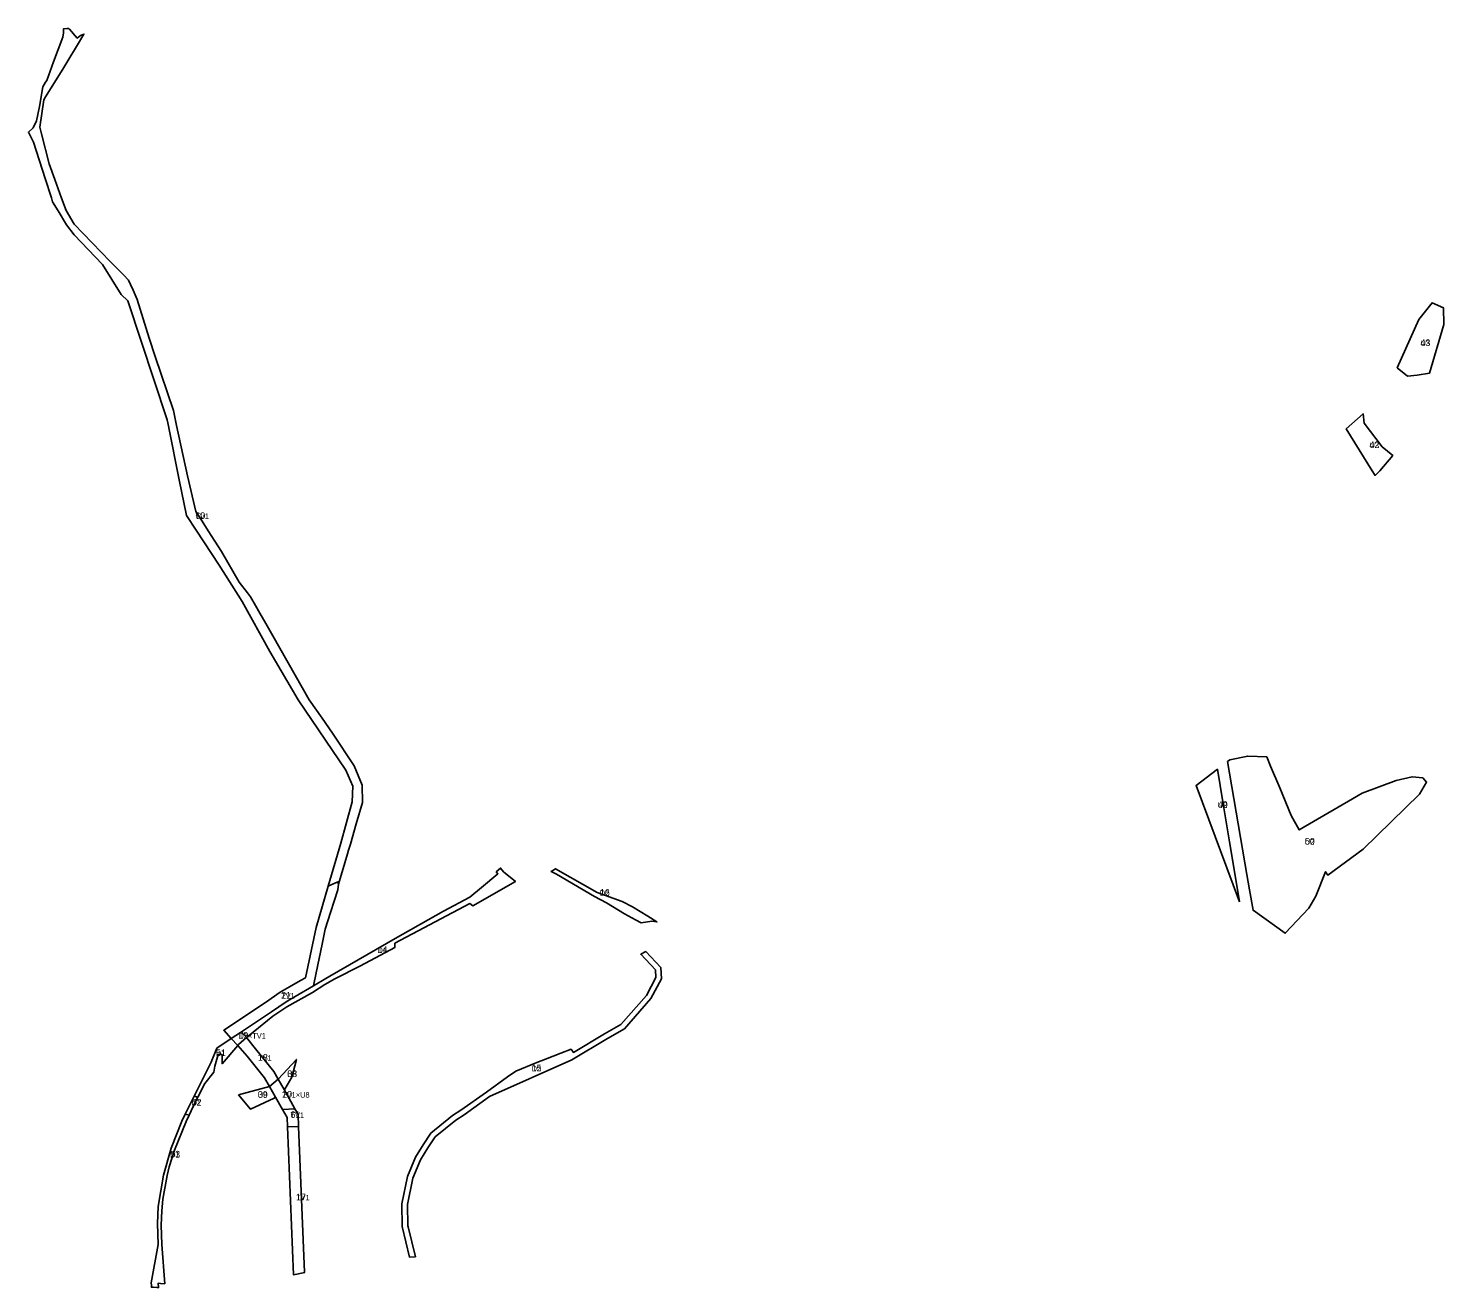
# Model space of a CAD drawing. Extents: x -521229 to -518220, y -1182332 to -1179899.
# Drawn here: x -519495 to -518220, y -1182332 to -1181197 of the extents above; entities that cross this region are included whole.
import ezdxf

# ---------------------------------------------------------------- set-up
doc = ezdxf.new("R2010")
doc.units = 0
for name, color, linetype in [('96120023', 7, 'Continuous'), ('96140023', 7, 'Continuous'), ('ID_VPO', 7, 'Continuous'), ('ID_VPS', 7, 'Continuous')]:
    doc.layers.add(name, color=color, linetype=linetype)

msp = doc.modelspace()

# ---------------------------------------------------------------- linework, layer by layer
at = {"layer": '96120023'}
for points in [[(-519215.9, -1181968.5), (-519216.5, -1181966.3), (-519225.2, -1181970.1), (-519213.9, -1181931.5), (-519203.5, -1181894.2), (-519203.1, -1181880), (-519209.3, -1181865.7), (-519252.2, -1181802.5), (-519277.7, -1181758.8), (-519302.6, -1181713.9), (-519323.6, -1181681.2), (-519344.2, -1181649.6), (-519352.9, -1181636.3), (-519359.6, -1181604.3), (-519368.7, -1181557.5), (-519368.7, -1181557.2), (-519370.4, -1181550.3), (-519405.7, -1181443.1), (-519411.7, -1181437.2), (-519428.5, -1181410.3), (-519454, -1181383.6), (-519461, -1181374.5), (-519468.4, -1181361.8), (-519473.5, -1181353.7), (-519474.6, -1181350.3), (-519480.4, -1181332.8), (-519490.9, -1181300.1), (-519495.4, -1181291), (-519491.1, -1181287.2), (-519488, -1181280.9), (-519485.4, -1181267.9), (-519482.4, -1181250.1), (-519479.9, -1181246), (-519478.9, -1181244.5), (-519472.7, -1181227.6), (-519464.3, -1181205.3), (-519463.8, -1181201.4), (-519463.7, -1181198.7), (-519463.8, -1181198), (-519460.8, -1181197.6), (-519459, -1181197.5), (-519458.4, -1181198.2), (-519451.4, -1181206.3), (-519448.5, -1181203.9), (-519445.4, -1181202.7), (-519450.3, -1181210.8), (-519460.7, -1181228.4), (-519464.3, -1181234.2), (-519480, -1181259.1), (-519481.6, -1181261.8), (-519485, -1181286.5), (-519483.7, -1181292.5), (-519476.7, -1181319.5), (-519471.5, -1181333.7), (-519465.4, -1181350.4), (-519461.3, -1181361.7), (-519454.1, -1181373.8), (-519421.6, -1181407.6), (-519412.6, -1181416.6), (-519409.4, -1181419.9), (-519405.1, -1181424.3), (-519403.4, -1181428.1), (-519401.1, -1181433.2), (-519397.5, -1181441.8), (-519386.5, -1181476.6), (-519381, -1181493), (-519364.6, -1181541.6), (-519362, -1181555.4), (-519351.9, -1181600.5), (-519344.5, -1181632.7), (-519338.9, -1181641.3), (-519333.4, -1181650.1), (-519321.4, -1181668.9), (-519305.3, -1181696.4), (-519298, -1181706), (-519296.2, -1181708.4), (-519295.1, -1181709.7), (-519290.8, -1181717.3), (-519286.8, -1181724.3), (-519281.3, -1181733.6), (-519242.4, -1181802.3), (-519230.7, -1181819), (-519221.3, -1181832.4), (-519201.8, -1181861.7), (-519194.5, -1181879.2), (-519194.4, -1181895), (-519199.9, -1181914), (-519205.1, -1181932.4), (-519206.8, -1181937.9), (-519207.7, -1181941.2)], [(-519263, -1182074.3), (-519254.9, -1182069.6), (-519238.3, -1182059.9), (-519227.2, -1182053.5), (-519223.6, -1182051.4), (-519165, -1182017.4), (-519121.4, -1181992.9), (-519097.7, -1181980.1), (-519087, -1181971.3), (-519072.3, -1181959), (-519073.7, -1181957.4), (-519069.8, -1181954), (-519067.1, -1181957.2), (-519056.5, -1181966.1), (-519094.9, -1181987.8), (-519097.7, -1181985.9), (-519165.3, -1182021.7), (-519165.2, -1182025.6), (-519196.2, -1182041.9), (-519219.1, -1182053.7), (-519228.3, -1182058.9), (-519239.4, -1182065.9), (-519262.5, -1182078.9), (-519275.1, -1182087.4), (-519292.8, -1182101.6), (-519298.8, -1182106.7), (-519303.2, -1182101.3), (-519276.2, -1182083.4)], [(-518937.3, -1181997.3), (-518929, -1182002.4), (-518933.6, -1182001.9), (-518943.3, -1182003.3), (-518948.4, -1182000.5), (-518958.2, -1181995.2), (-518974.5, -1181985.3), (-518985.3, -1181979.5), (-519019.5, -1181959.3), (-519024.4, -1181957.1), (-519020.5, -1181954.6), (-518982.7, -1181976), (-518960.3, -1181984.1), (-518951, -1181988.9)], [(-519216.5, -1181966.3), (-519215.9, -1181968.5), (-519216.6, -1181973.6), (-519223.2, -1181994.1), (-519227.9, -1182009), (-519230.7, -1182022.6), (-519235.9, -1182048.3), (-519238.3, -1182059.9), (-519254.9, -1182069.6), (-519263, -1182074.3), (-519276.2, -1182083.4), (-519303.2, -1182101.3), (-519304.1, -1182101.9), (-519312.5, -1182107.5), (-519319.3, -1182100), (-519281.8, -1182075.1), (-519268.4, -1182065.8), (-519260, -1182061), (-519250.1, -1182055.2), (-519245.6, -1182052.7), (-519236.1, -1182007.6), (-519225.2, -1181970.1)], [(-519153.4, -1182276.3), (-519153.2, -1182277.2), (-519146.6, -1182304.1), (-519152, -1182304.4), (-519158.4, -1182276.9), (-519158.7, -1182256.5), (-519153.6, -1182231.9), (-519146.4, -1182214.4), (-519139.6, -1182203.3), (-519132.6, -1182192.7), (-519113.1, -1182176.9), (-519105.6, -1182172), (-519082.7, -1182155.7), (-519063.6, -1182141.9), (-519056.2, -1182136.9), (-519037.1, -1182129.2), (-519029.5, -1182126.1), (-519015.7, -1182120.8), (-519006.3, -1182117.1), (-519004.2, -1182120), (-518976.2, -1182103.2), (-518961.4, -1182094.7), (-518938.5, -1182068.6), (-518930.1, -1182052.6), (-518930.3, -1182045.5), (-518943.5, -1182031.6), (-518939, -1182029.1), (-518925.4, -1182043.5), (-518925, -1182053.8), (-518934.4, -1182071.5), (-518958.2, -1182098.6), (-518973.6, -1182107.5), (-519005.6, -1182126.6), (-519079.8, -1182159.8), (-519102.8, -1182176.1), (-519110.2, -1182181), (-519128.9, -1182196.1), (-519135.4, -1182206), (-519141.9, -1182216.7), (-519148.8, -1182233.3), (-519153.7, -1182257)], [(-519304.1, -1182101.9), (-519303.2, -1182101.3), (-519298.8, -1182106.7), (-519306, -1182112.9), (-519306.7, -1182113.8), (-519312.5, -1182107.5)], [(-519325.6, -1182116.1), (-519312.5, -1182107.5), (-519306.7, -1182113.8), (-519320.9, -1182130.2), (-519320.8, -1182121.9), (-519324.4, -1182121.8), (-519327.5, -1182132.3), (-519328.2, -1182137.9), (-519336.5, -1182148), (-519342.7, -1182160.2), (-519346.1, -1182159.4), (-519330.8, -1182128.7)], [(-519274.2, -1182137.3), (-519270.3, -1182144.2), (-519278.2, -1182150.6), (-519282.5, -1182142.9), (-519298.1, -1182123.5), (-519306.7, -1182113.8), (-519306, -1182112.9), (-519298.8, -1182106.7), (-519290.8, -1182116.7)], [(-519265, -1182153.5), (-519259, -1182164.2), (-519255.3, -1182170.8), (-519266.4, -1182171.5), (-519272.8, -1182160.2), (-519278.2, -1182150.6), (-519270.3, -1182144.2)], [(-519346.1, -1182159.4), (-519342.7, -1182160.2), (-519344.7, -1182164.2), (-519350.4, -1182176.4), (-519354, -1182175.6), (-519347.5, -1182162.4)], [(-519357, -1182181.9), (-519354, -1182175.6), (-519350.4, -1182176.4), (-519353.1, -1182182.1), (-519363.6, -1182208.1), (-519368.5, -1182223), (-519370.4, -1182230.8), (-519374.2, -1182252.1), (-519375.2, -1182262.6), (-519375.7, -1182275.6), (-519375, -1182293.1), (-519372.5, -1182328.4), (-519376.2, -1182328.1), (-519378.5, -1182328), (-519378.1, -1182331.9), (-519379.7, -1182331.8), (-519382.8, -1182331.6), (-519384.5, -1182331.5), (-519384.3, -1182329.7), (-519384.8, -1182327.5), (-519378.5, -1182293.1), (-519378.9, -1182274.2), (-519378.3, -1182258.9), (-519373.6, -1182230.6), (-519366.8, -1182206.1)], [(-519255.3, -1182170.8), (-519252.4, -1182175.8), (-519252, -1182186.8), (-519262, -1182187.1), (-519262.3, -1182178.6), (-519266.4, -1182171.5)], [(-519252, -1182186.8), (-519246.6, -1182317.8), (-519246.4, -1182318.2), (-519256.5, -1182320.2), (-519262, -1182187.1)]]:
    msp.add_lwpolyline(points, close=True, dxfattribs=at)
at = {"layer": '96140023'}
for points in [[(-518252.5, -1181510.9), (-518261.8, -1181503.3), (-518242.4, -1181459.7), (-518230.4, -1181444.7), (-518220.1, -1181449.3), (-518220, -1181464.4), (-518232.9, -1181508.2), (-518243.8, -1181510)], [(-518284.3, -1181596.1), (-518307.8, -1181558.4), (-518292.6, -1181544.7), (-518291.5, -1181553.1), (-518275.5, -1181574.4), (-518265.9, -1181582.4), (-518277.6, -1181596.1), (-518281.8, -1181600.2)], [(-518412.8, -1181856.5), (-518396.5, -1181853), (-518379.5, -1181853.8), (-518376.1, -1181862.1), (-518367.7, -1181881.6), (-518357.5, -1181906.6), (-518350.2, -1181919.6), (-518302.1, -1181891.7), (-518293.4, -1181886.5), (-518262.9, -1181874.9), (-518248.5, -1181871.6), (-518238.8, -1181872.7), (-518235.4, -1181876.6), (-518241.7, -1181887.3), (-518292.4, -1181936.8), (-518324.5, -1181960.2), (-518326.4, -1181957.3), (-518335.1, -1181979.1), (-518341.4, -1181989.9), (-518362.7, -1182012.6), (-518391.7, -1181991.9), (-518394.9, -1181973.6), (-518397.3, -1181959.6), (-518414.9, -1181858)], [(-518403.9, -1181984.2), (-518443.1, -1181879.4), (-518423.9, -1181864.9), (-518418.9, -1181894.4), (-518412.9, -1181930.3), (-518408.7, -1181955.2)], [(-519265, -1182153.5), (-519270.3, -1182144.2), (-519253.9, -1182126.3), (-519257.9, -1182142.4), (-519264.4, -1182153)], [(-519305.9, -1182158.1), (-519278.2, -1182150.6), (-519272.8, -1182160.2), (-519272.8, -1182160.2), (-519273.8, -1182161.1), (-519295.3, -1182171.1)], [(-519265, -1182153.5), (-519259, -1182164.2), (-519255.3, -1182170.8), (-519266.4, -1182171.5), (-519272.8, -1182160.2), (-519278.2, -1182150.6), (-519270.3, -1182144.2)]]:
    msp.add_lwpolyline(points, close=True, dxfattribs=at)

# ---------------------------------------------------------------- texts
at = {"layer": '96120023'}
for s, rotation, p in [('TV1', 360, (-519344.9, -1181639.5)), ('D2', 0, (-518980.4, -1181978.9)), ('D1', 0, (-519180.8, -1182030.4)), ('TV1', 0, (-519267.6, -1182071.5)), ('D1×TV1', 360, (-519306.1, -1182107.6)), ('D1', 360, (-519326.4, -1182123.3)), ('TV1', 0, (-519288.5, -1182127.5)), ('D2', 360, (-519041.9, -1182137)), ('TV1×U8', 360, (-519266.7, -1182160.7)), ('D1', 360, (-519348.3, -1182167.9)), ('TV1', 0, (-519259.2, -1182179)), ('D1', 360, (-519367.6, -1182214.7)), ('TV1', 360, (-519254.2, -1182253.3))]:
    msp.add_text(s, height=5, rotation=rotation, dxfattribs=at).set_placement(p)
at = {"layer": '96140023'}
for s, rotation, p in [('U3', 360, (-518240.9, -1181483.7)), ('U3', 0, (-518286.8, -1181575.6)), ('U2', 360, (-518423.5, -1181899.7)), ('U2', 0, (-518345.1, -1181932.8)), ('U8', 0, (-519262.1, -1182142.2)), ('U8', 0, (-519288.6, -1182160.9)), ('TV1×U8', 360, (-519266.7, -1182160.7))]:
    msp.add_text(s, height=5, rotation=rotation, dxfattribs=at).set_placement(p)
at = {"layer": 'ID_VPO'}
for s, rotation, p in [('43', 0, (-518240.9, -1181483.7)), ('42', 0, (-518286.8, -1181575.6)), ('49', 0, (-518423.5, -1181899.7)), ('50', 360, (-518345.1, -1181932.8)), ('38', 0, (-519262.1, -1182142.2)), ('39', 360, (-519288.6, -1182160.9)), ('20', 360, (-519266.7, -1182160.7))]:
    msp.add_text(s, height=6, rotation=rotation, dxfattribs=at).set_placement(p)
at = {"layer": 'ID_VPS'}
for s, rotation, p in [('60', 360, (-519344.9, -1181639.5)), ('16', 0, (-518980.4, -1181978.9)), ('14', 360, (-519180.8, -1182030.4)), ('21', 0, (-519267.6, -1182071.5)), ('19', 0, (-519306.1, -1182107.6)), ('51', 360, (-519326.4, -1182123.3)), ('18', 0, (-519288.5, -1182127.5)), ('15', 0, (-519041.9, -1182137)), ('20', 360, (-519266.7, -1182160.7)), ('52', 0, (-519348.3, -1182167.9)), ('61', 0, (-519259.2, -1182179)), ('53', 0, (-519367.6, -1182214.7)), ('17', 360, (-519254.2, -1182253.3))]:
    msp.add_text(s, height=6, rotation=rotation, dxfattribs=at).set_placement(p)

doc.saveas('drawing.dxf')
